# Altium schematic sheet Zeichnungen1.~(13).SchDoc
size A4; PageSetup: Record=PageOptions¦CenterHorizontal=True¦CenterVertical=True¦PrintScale=1.00¦XCorrection=1.00¦YCorrection=1.00¦PrintKind=0¦BorderSize=5000000¦LeftOffset=0¦BottomOffset=0¦Orientation=2¦PaperLength=1000¦PaperWidth=1000¦Scale=100¦PaperSource=7¦PrintQuality=-3¦MediaType=1¦DitherType=10¦PrintScaleMode=1¦PaperKind=A4¦PaperIndex=9
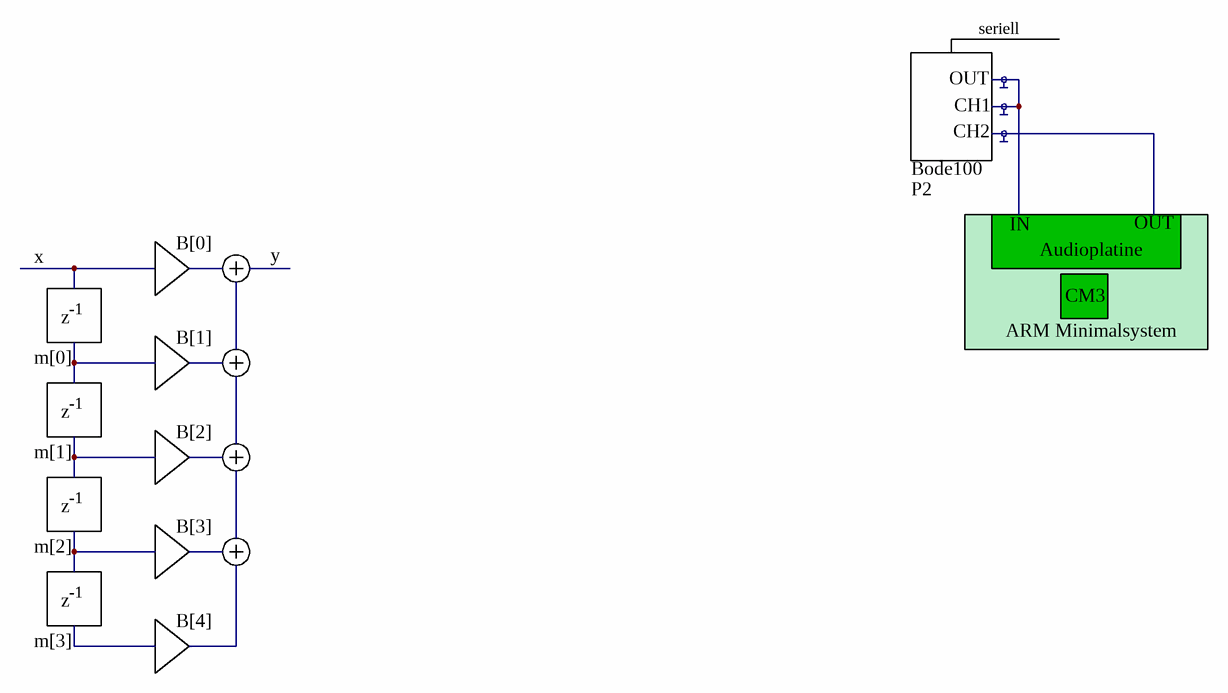
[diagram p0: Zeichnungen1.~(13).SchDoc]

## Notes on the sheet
- seriell
- OUT
- CH2
- CH1
- Bode100
- P2
- x
- B[0]
- y
- IN
- Audioplatine
- z
- -1
- B[1]
- ARM Minimalsystem
- CM3
- m[0]
- m[1]
- B[2]
- B[3]
- m[2]
- m[3]
- B[4]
